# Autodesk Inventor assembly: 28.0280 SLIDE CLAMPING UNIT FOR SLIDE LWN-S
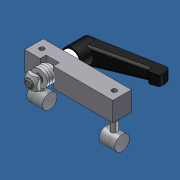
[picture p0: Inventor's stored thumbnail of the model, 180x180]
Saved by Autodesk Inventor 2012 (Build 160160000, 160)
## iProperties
Created: 2007-06
Part Number: 28.0280 SLIDE CLAMPING UNIT FOR SLIDE LWN-S
Document SubType Name: Assembly
Designer: Andy Moles
Description: MACHINE TO 28.0280/9
Mass: 267.869 g
Surface Area: 228.812 cm^2
Volume: 58.3866 cm^3
Density: 4.58786 g/cm^3
Vendor: V
Author: Andy Moles
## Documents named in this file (8)
- C:\Andys Backup Data\ANDY'S INVENTOR\INVENTOR LIBRARIES\PARTS LIBRARY\READY FOR USE MODULES LG\SUBCOMPONENTS\28.0280 SLIDE CLAMPING UNIT FOR SLIDE LWN-S.iam
- C:\Andys Backup Data\ANDY'S INVENTOR\INVENTOR LIBRARIES\PARTS LIBRARY\FASTENING ELEMENTS\WASHERS\WASHER M8 PLASTIC 17mm OD.ipt
- C:\Andys Backup Data\ANDY'S INVENTOR\INVENTOR LIBRARIES\PARTS LIBRARY\COMPONENTS LR\SUBCOMPONENTS\28.0270 SLIDE CLAMPING UNIT HANDLE.ipt
- C:\Andys Backup Data\ANDY'S INVENTOR\INVENTOR LIBRARIES\PARTS LIBRARY\COMPONENTS LR\SUBCOMPONENTS\28.0271 THREADED STUD.ipt
- C:\Andys Backup Data\ANDY'S INVENTOR\INVENTOR LIBRARIES\PARTS LIBRARY\FASTENING ELEMENTS\NUTS\21.1351 M8 SQUARE NUT.ipt
- C:\Andys Backup Data\ANDY'S INVENTOR\INVENTOR LIBRARIES\PARTS LIBRARY\READY FOR USE MODULES LG\SUBCOMPONENTS\28.0280 SLIDE CLAMPING AL BLOCK FOR SLIDE LWN-S.ipt
- C:\Andys Backup Data\ANDY'S INVENTOR\INVENTOR LIBRARIES\PARTS LIBRARY\FASTENING ELEMENTS\SUBCOMPONENTS\21.1024 BOLT FASTENER 15.ipt
- C:\Andys Backup Data\ANDY'S INVENTOR\INVENTOR LIBRARIES\PARTS LIBRARY\FASTENING ELEMENTS\SCREWS CAP\21.1245 M6X35.ipt
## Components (12 placed, 7 different names)
1. 28.0280 SLIDE CLAMPING AL BLOCK FOR SLIDE LWN-S:1 — Angle:2, Insert:12, Angle:3, Flush:1, Flush:2, Mate:8, Mate:9, Flush:3, Flush:4, Mate:10, Angle:4
2. WASHER M8 PLASTIC 17mm OD:1 — Insert:13, Insert:14
3. WASHER M8 PLASTIC 17mm OD:3 — Insert:15, Flush:1, Mate:7
4. 28.0270 SLIDE CLAMPING UNIT HANDLE:1 — Insert:11, Insert:12, Angle:4
5. 28.0271 THREADED STUD:1 — Insert:11, Mate:5, Mate:6
6. 21.1351 M8 SQUARE NUT:1 — Mate:5, Angle:3, Insert:13
7. 21.1351 M8 SQUARE NUT:2 — Angle:2, Mate:6, Mate:7
8. WASHER M8 PLASTIC 17mm OD:4 — Insert:14, Insert:15
9. 21.1024 BOLT FASTENER 15:1 — Flush:2, Mate:8, Mate:9, Insert:17
10. 21.1024 BOLT FASTENER 15:2 — Flush:3, Flush:4, Mate:10, Insert:16
11. 21.1245  M6 x 35:1 — Insert:16
12. 21.1245  M6 x 35:2 — Insert:17
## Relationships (20: Insert 7, Mate 6, Flush 4, Angle 3)
- Insert:11: 28.0270 SLIDE CLAMPING UNIT HANDLE:1 ↔ 28.0271 THREADED STUD:1
- Angle:2: 28.0280 SLIDE CLAMPING AL BLOCK FOR SLIDE LWN-S:1 ↔ 21.1351 M8 SQUARE NUT:2
- Insert:12: 28.0280 SLIDE CLAMPING AL BLOCK FOR SLIDE LWN-S:1 ↔ 28.0270 SLIDE CLAMPING UNIT HANDLE:1
- Mate:5: 28.0271 THREADED STUD:1 ↔ 21.1351 M8 SQUARE NUT:1
- Angle:3: 28.0280 SLIDE CLAMPING AL BLOCK FOR SLIDE LWN-S:1 ↔ 21.1351 M8 SQUARE NUT:1
- Insert:13: WASHER M8 PLASTIC 17mm OD:1 ↔ 21.1351 M8 SQUARE NUT:1
- Insert:14: WASHER M8 PLASTIC 17mm OD:1 ↔ WASHER M8 PLASTIC 17mm OD:4
- Insert:15: WASHER M8 PLASTIC 17mm OD:3 ↔ WASHER M8 PLASTIC 17mm OD:4
- Mate:6: 28.0271 THREADED STUD:1 ↔ 21.1351 M8 SQUARE NUT:2
- Flush:1: 28.0280 SLIDE CLAMPING AL BLOCK FOR SLIDE LWN-S:1 ↔ WASHER M8 PLASTIC 17mm OD:3
- Mate:7: WASHER M8 PLASTIC 17mm OD:3 ↔ 21.1351 M8 SQUARE NUT:2
- Flush:2: 28.0280 SLIDE CLAMPING AL BLOCK FOR SLIDE LWN-S:1 ↔ 21.1024 BOLT FASTENER 15:1
- Mate:8: 28.0280 SLIDE CLAMPING AL BLOCK FOR SLIDE LWN-S:1 ↔ 21.1024 BOLT FASTENER 15:1
- Mate:9: 28.0280 SLIDE CLAMPING AL BLOCK FOR SLIDE LWN-S:1 ↔ 21.1024 BOLT FASTENER 15:1
- Flush:3: 28.0280 SLIDE CLAMPING AL BLOCK FOR SLIDE LWN-S:1 ↔ 21.1024 BOLT FASTENER 15:2
- Flush:4: 28.0280 SLIDE CLAMPING AL BLOCK FOR SLIDE LWN-S:1 ↔ 21.1024 BOLT FASTENER 15:2
- Mate:10: 28.0280 SLIDE CLAMPING AL BLOCK FOR SLIDE LWN-S:1 ↔ 21.1024 BOLT FASTENER 15:2
- Insert:16: 21.1024 BOLT FASTENER 15:2 ↔ 21.1245  M6 x 35:1
- Insert:17: 21.1024 BOLT FASTENER 15:1 ↔ 21.1245  M6 x 35:2
- Angle:4: 28.0280 SLIDE CLAMPING AL BLOCK FOR SLIDE LWN-S:1 ↔ 28.0270 SLIDE CLAMPING UNIT HANDLE:1
